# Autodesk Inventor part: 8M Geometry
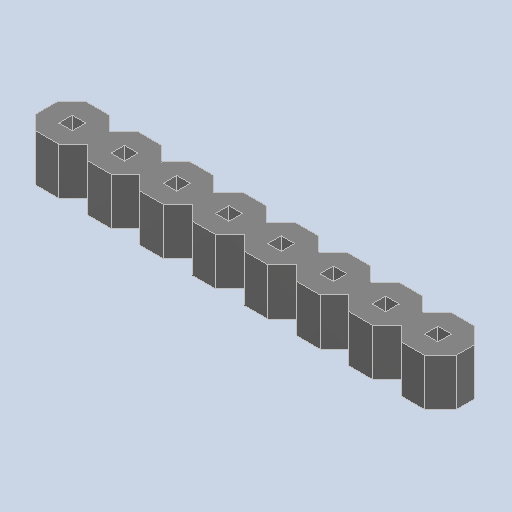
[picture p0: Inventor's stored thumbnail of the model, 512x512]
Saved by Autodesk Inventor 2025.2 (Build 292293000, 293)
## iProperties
Created: 2025-04
Part Number: 8M Geometry
Material: Generic
Description: PART-8M Geometry-DESC
Document SubType Name: Modeling
Designer: BennF
Density: 1 g/cm^3
Appearance: Default
Author: BennF
Revision Number: NONE
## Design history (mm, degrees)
feature "8"
body "Solid1"
